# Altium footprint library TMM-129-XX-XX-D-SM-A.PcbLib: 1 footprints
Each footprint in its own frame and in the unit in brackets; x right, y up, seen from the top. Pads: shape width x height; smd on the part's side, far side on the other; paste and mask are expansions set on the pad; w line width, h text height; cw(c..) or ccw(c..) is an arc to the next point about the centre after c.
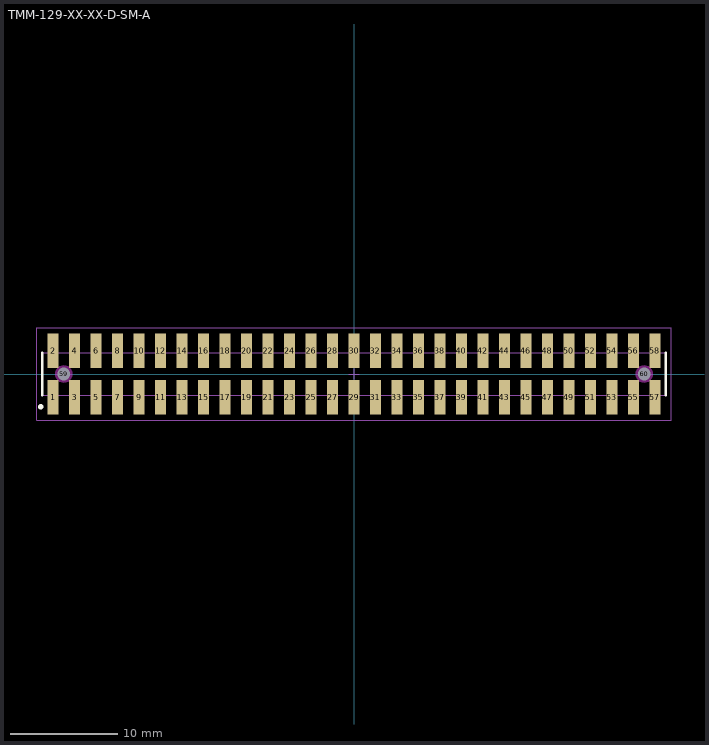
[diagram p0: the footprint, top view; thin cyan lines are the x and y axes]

## TMM-129-XX-XX-D-SM-A [mm] "2.00mm pitch, 58 pin, terminal strip; double row, w/alignment pins, SMT"
height 2.77
pads (60):
  rect 1x3.2 smd mask+0: 1(-28,-2.15) 2(-28,2.15) 3(-26,-2.15) 4(-26,2.15) 5(-24,-2.15) 6(-24,2.15) 7(-22,-2.15) 8(-22,2.15) 9(-20,-2.15) 10(-20,2.15) 11(-18,-2.15) 12(-18,2.15) 13(-16,-2.15) 14(-16,2.15) 15(-14,-2.15) 16(-14,2.15) 17(-12,-2.15) 18(-12,2.15) 19(-10,-2.15) 20(-10,2.15) 21(-8,-2.15) 22(-8,2.15) 23(-6,-2.15) 24(-6,2.15) 25(-4,-2.15) 26(-4,2.15) 27(-2,-2.15) 28(-2,2.15) 29(0,-2.15) 30(0,2.15) 31(2,-2.15) 32(2,2.15) 33(4,-2.15) 34(4,2.15) 35(6,-2.15) 36(6,2.15) 37(8,-2.15) 38(8,2.15) 39(10,-2.15) 40(10,2.15) 41(12,-2.15) 42(12,2.15) 43(14,-2.15) 44(14,2.15) 45(16,-2.15) 46(16,2.15) 47(18,-2.15) 48(18,2.15) 49(20,-2.15) 50(20,2.15) 51(22,-2.15) 52(22,2.15) 53(24,-2.15) 54(24,2.15) 55(26,-2.15) 56(26,2.15) 57(28,-2.15) 58(28,2.15)
  round 1 hole 1.2 unplated mask+0: 59(-27,0) 60(27,0)
Top Overlay:
  circle w0.25: c-29.15,-3.05 r0.125
  lines w0.2: -29,-2 -29,2 ; 29,-2 29,2
Keep-Out Layer:
  pour cut-out: 27.807,0 27.779,0.209 27.699,0.403 27.57,0.571 27.403,0.699 27.209,0.779 27,0.807 26.791,0.779 26.596,0.699 26.429,0.571 26.301,0.403 26.22,0.209 26.193,0 26.22,-0.209 26.301,-0.403 26.429,-0.571 26.596,-0.699 26.791,-0.779 27,-0.807 27.209,-0.779 27.403,-0.699 27.57,-0.571 27.699,-0.403 27.779,-0.209
  pour cut-out: -26.193,0 -26.22,0.209 -26.301,0.403 -26.429,0.571 -26.596,0.699 -26.791,0.779 -27,0.807 -27.209,0.779 -27.403,0.699 -27.57,0.571 -27.699,0.403 -27.779,0.209 -27.807,0 -27.779,-0.209 -27.699,-0.403 -27.57,-0.571 -27.403,-0.699 -27.209,-0.779 -27,-0.807 -26.791,-0.779 -26.596,-0.699 -26.429,-0.571 -26.301,-0.403 -26.22,-0.209
Mechanical 12:
  lines w0.001: -29,-2 -29,2 29,2 29,-2 -29,-2
Mechanical 13:
  lines w0.1: -29,-2 -29,2 29,2 29,-2 -29,-2
  text ".Designator" at 0,-0.127 h1.52
Mechanical 15:
  lines w0.05: -0.5,0 0.5,0 ; 0,-0.5 0,0.5 ; -29.5,-4.3 -29.5,4.3 29.5,4.3 29.5,-4.3 -29.5,-4.3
